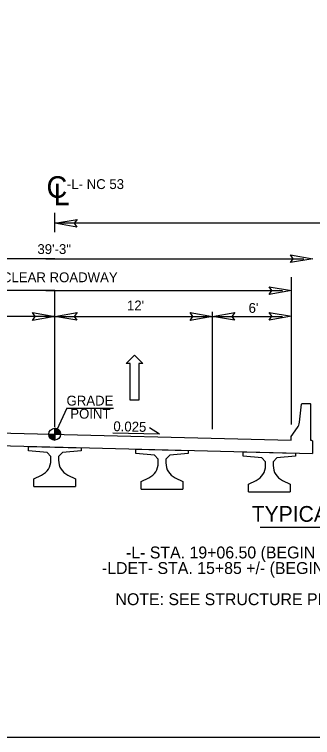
# Model space of a CAD drawing. Extents: x 1548135 to 1549339, y 868664 to 869085.
# Drawn here: x 1548186.8 to 1548209.5, y 868664.3 to 868719.3 of the extents above; entities that cross this region are included whole.
import ezdxf

# ---------------------------------------------------------------- set-up
doc = ezdxf.new("R2010")
doc.units = 0
for name, color, linetype in [('Default', 7, 'Continuous'), ('P_RDY_TC_Pvmt_Asphalt_Base_Course', 7, 'Continuous'), ('Sheet_Title_Block_Text', 7, 'Continuous'), ('Typical Bridge Rail CELL', 7, 'Continuous'), ('Typical Curb CELL', 7, 'Continuous'), ('Typical Grade Point Symbol CELL', 7, 'Continuous'), ('Typical Hinge Slope Arterial CELL', 7, 'Continuous'), ('Typical Hinge Slope Interstate CELL', 7, 'Continuous'), ('Typical Pavement Slope Information CELL', 7, 'Continuous'), ('Typical Shoulder Slope CELL', 7, 'Continuous'), ('Typical Shoulder Slope Information CELL', 7, 'Continuous'), ('Typical Terminator CELL', 7, 'Continuous'), ('Typical Text General CELL', 7, 'Continuous'), ('Typical Text ID Circle CELL', 7, 'Continuous')]:
    doc.layers.add(name, color=color, linetype=linetype)

msp = doc.modelspace()

# ---------------------------------------------------------------- linework, layer by layer
at = {"layer": 'Default'}
msp.add_lwpolyline([(1548135.05, 868774.324), (1548305.05, 868774.324), (1548305.05, 868664.324), (1548135.05, 868664.324)], close=True, dxfattribs=at)
at = {"layer": 'P_RDY_TC_Pvmt_Asphalt_Base_Course'}
for points in [[(1548191.54, 868703.148), (1548189.853, 868703.439), (1548191.55, 868703.739), (1548191.334, 868703.439)], [(1548207.801, 868701.037), (1548209.489, 868700.746), (1548207.792, 868700.446), (1548208.008, 868700.746)], [(1548206.176, 868698.613), (1548207.864, 868698.322), (1548206.167, 868698.022), (1548206.383, 868698.322)], [(1548188.165, 868696.642), (1548189.853, 868696.351), (1548188.156, 868696.051), (1548188.371, 868696.351)], [(1548191.54, 868696.061), (1548189.853, 868696.351), (1548191.55, 868696.651), (1548191.334, 868696.351)], [(1548200.165, 868696.642), (1548201.853, 868696.351), (1548200.156, 868696.051), (1548200.371, 868696.351)], [(1548203.54, 868696.061), (1548201.853, 868696.351), (1548203.55, 868696.651), (1548203.334, 868696.351)], [(1548206.176, 868696.66), (1548207.864, 868696.369), (1548206.167, 868696.069), (1548206.383, 868696.369)]]:
    msp.add_lwpolyline(points, close=True, dxfattribs=at)
at = {"layer": 'Typical Bridge Rail CELL'}
for p, q in [((1548187.853, 868686.13), (1548187.853, 868686.471)), ((1548187.853, 868686.471), (1548191.853, 868686.371)), ((1548189.269, 868686.005), (1548187.853, 868686.13)), ((1548189.561, 868685.713), (1548189.269, 868686.005)), ((1548190.436, 868686.005), (1548190.144, 868685.713)), ((1548191.853, 868686.13), (1548190.436, 868686.005)), ((1548191.853, 868686.371), (1548191.853, 868686.13)), ((1548196.019, 868685.926), (1548196.019, 868686.267)), ((1548196.019, 868686.267), (1548200.019, 868686.167)), ((1548200.019, 868686.167), (1548200.019, 868685.926)), ((1548204.186, 868685.721), (1548204.186, 868686.063)), ((1548204.186, 868686.063), (1548208.186, 868685.963)), ((1548208.186, 868685.963), (1548208.186, 868685.721)), ((1548189.561, 868685.413), (1548189.561, 868685.713)), ((1548190.144, 868685.713), (1548190.144, 868685.413)), ((1548197.436, 868685.801), (1548196.019, 868685.926)), ((1548197.728, 868685.509), (1548197.436, 868685.801)), ((1548197.728, 868685.209), (1548197.728, 868685.509)), ((1548198.603, 868685.801), (1548198.311, 868685.509)), ((1548198.311, 868685.509), (1548198.311, 868685.209)), ((1548200.019, 868685.926), (1548198.603, 868685.801)), ((1548205.603, 868685.596), (1548204.186, 868685.721)), ((1548205.894, 868685.305), (1548205.603, 868685.596)), ((1548206.769, 868685.596), (1548206.478, 868685.305)), ((1548208.186, 868685.721), (1548206.769, 868685.596)), ((1548205.894, 868685.005), (1548205.894, 868685.305)), ((1548206.478, 868685.305), (1548206.478, 868685.005)), ((1548188.269, 868684.005), (1548188.855, 868684.288)), ((1548188.269, 868683.421), (1548188.269, 868684.005)), ((1548190.85, 868684.288), (1548191.436, 868684.005)), ((1548191.436, 868684.005), (1548191.436, 868683.421)), ((1548196.436, 868683.801), (1548197.022, 868684.084)), ((1548196.436, 868683.217), (1548196.436, 868683.801)), ((1548199.017, 868684.084), (1548199.603, 868683.801)), ((1548199.603, 868683.801), (1548199.603, 868683.217)), ((1548204.603, 868683.596), (1548205.189, 868683.88)), ((1548207.183, 868683.88), (1548207.769, 868683.596)), ((1548188.269, 868683.421), (1548191.436, 868683.421)), ((1548196.436, 868683.217), (1548199.603, 868683.217)), ((1548204.603, 868683.013), (1548204.603, 868683.596)), ((1548207.769, 868683.596), (1548207.769, 868683.013)), ((1548204.603, 868683.013), (1548207.769, 868683.013))]:
    msp.add_line(p, q, dxfattribs=at)
for centre, start, end in [((1548188.311, 868685.413), 295.821, 0), ((1548191.394, 868685.413), 180, 244.179), ((1548196.478, 868685.209), 295.821, 0), ((1548199.561, 868685.209), 180, 244.179), ((1548204.644, 868685.005), 295.821, 0), ((1548207.728, 868685.005), 180, 244.179)]:
    msp.add_arc(centre, 1.25, start, end, dxfattribs=at)
at = {"layer": 'Typical Curb CELL'}
for p, q in [((1548189.853, 868687.399), (1548189.853, 868687.847)), ((1548189.405, 868687.399), (1548189.853, 868687.399)), ((1548189.852, 868686.952), (1548189.853, 868687.399)), ((1548189.853, 868687.399), (1548189.852, 868686.952)), ((1548190.3, 868687.399), (1548189.853, 868687.399))]:
    msp.add_line(p, q, dxfattribs=at)
for points in [[(1548189.857, 868687.847), (1548189.857, 868687.847), (1548189.857, 868687.399)], [(1548189.866, 868687.847), (1548189.866, 868687.399)], [(1548189.875, 868687.846), (1548189.875, 868687.399)], [(1548189.884, 868687.846), (1548189.884, 868687.399)], [(1548189.893, 868687.845), (1548189.893, 868687.399)], [(1548189.902, 868687.844), (1548189.902, 868687.399)], [(1548189.911, 868687.843), (1548189.911, 868687.399)], [(1548189.92, 868687.842), (1548189.92, 868687.399)], [(1548189.929, 868687.841), (1548189.929, 868687.399)], [(1548189.937, 868687.839), (1548189.937, 868687.399)], [(1548189.946, 868687.837), (1548189.946, 868687.399)], [(1548189.955, 868687.835), (1548189.955, 868687.399)], [(1548189.964, 868687.833), (1548189.964, 868687.399)], [(1548189.973, 868687.83), (1548189.973, 868687.399)], [(1548189.982, 868687.828), (1548189.982, 868687.399)], [(1548189.991, 868687.825), (1548189.991, 868687.399)], [(1548190, 868687.822), (1548190, 868687.399)], [(1548190.009, 868687.819), (1548190.009, 868687.399)], [(1548190.018, 868687.815), (1548190.018, 868687.399)], [(1548190.027, 868687.811), (1548190.027, 868687.399)], [(1548190.036, 868687.807), (1548190.036, 868687.399)], [(1548190.045, 868687.803), (1548190.045, 868687.399)], [(1548190.054, 868687.799), (1548190.054, 868687.399)], [(1548190.063, 868687.794), (1548190.063, 868687.399)], [(1548190.072, 868687.789), (1548190.072, 868687.399)], [(1548190.081, 868687.784), (1548190.081, 868687.399)], [(1548190.09, 868687.779), (1548190.09, 868687.399)], [(1548190.099, 868687.773), (1548190.099, 868687.399)], [(1548190.108, 868687.767), (1548190.108, 868687.399)], [(1548190.117, 868687.76), (1548190.117, 868687.399)], [(1548190.125, 868687.754), (1548190.125, 868687.399)], [(1548190.134, 868687.747), (1548190.134, 868687.399)], [(1548190.143, 868687.739), (1548190.143, 868687.399)], [(1548190.152, 868687.731), (1548190.152, 868687.399)], [(1548190.161, 868687.723), (1548190.161, 868687.399)], [(1548190.17, 868687.715), (1548190.17, 868687.399)], [(1548190.179, 868687.706), (1548190.179, 868687.399)], [(1548190.188, 868687.696), (1548190.188, 868687.399)], [(1548190.197, 868687.685), (1548190.197, 868687.399)], [(1548190.206, 868687.674), (1548190.206, 868687.399)], [(1548190.215, 868687.662), (1548190.215, 868687.399)], [(1548190.224, 868687.649), (1548190.224, 868687.399)], [(1548190.233, 868687.635), (1548190.233, 868687.399)], [(1548190.242, 868687.62), (1548190.242, 868687.399)], [(1548190.251, 868687.604), (1548190.251, 868687.399)], [(1548189.407, 868687.399), (1548189.407, 868687.35)], [(1548189.416, 868687.399), (1548189.416, 868687.298)], [(1548189.425, 868687.399), (1548189.425, 868687.266)], [(1548189.434, 868687.399), (1548189.434, 868687.239)], [(1548189.443, 868687.399), (1548189.443, 868687.218)], [(1548189.452, 868687.399), (1548189.452, 868687.199)], [(1548189.461, 868687.399), (1548189.461, 868687.182)], [(1548189.47, 868687.399), (1548189.47, 868687.166)], [(1548189.479, 868687.399), (1548189.479, 868687.153)], [(1548189.488, 868687.399), (1548189.488, 868687.14)], [(1548189.497, 868687.399), (1548189.497, 868687.128)], [(1548189.506, 868687.399), (1548189.506, 868687.117)], [(1548189.515, 868687.399), (1548189.515, 868687.106)], [(1548189.524, 868687.399), (1548189.524, 868687.096)], [(1548189.533, 868687.399), (1548189.533, 868687.086)], [(1548189.542, 868687.399), (1548189.542, 868687.077)], [(1548189.551, 868687.399), (1548189.551, 868687.069)], [(1548189.56, 868687.399), (1548189.56, 868687.061)], [(1548189.568, 868687.399), (1548189.568, 868687.053)], [(1548189.577, 868687.399), (1548189.577, 868687.046)], [(1548189.586, 868687.399), (1548189.586, 868687.039)], [(1548189.595, 868687.399), (1548189.595, 868687.033)], [(1548189.604, 868687.399), (1548189.604, 868687.027)], [(1548189.613, 868687.399), (1548189.613, 868687.021)], [(1548189.622, 868687.399), (1548189.622, 868687.015)], [(1548189.631, 868687.399), (1548189.631, 868687.01)], [(1548189.64, 868687.399), (1548189.64, 868687.005)], [(1548189.649, 868687.399), (1548189.649, 868687)], [(1548189.658, 868687.399), (1548189.658, 868686.996)], [(1548189.667, 868687.399), (1548189.667, 868686.992)], [(1548189.676, 868687.399), (1548189.676, 868686.988)], [(1548189.685, 868687.399), (1548189.685, 868686.984)], [(1548189.694, 868687.399), (1548189.694, 868686.98)], [(1548189.703, 868687.399), (1548189.703, 868686.977)], [(1548189.712, 868687.399), (1548189.712, 868686.975)], [(1548189.721, 868687.399), (1548189.721, 868686.971)], [(1548189.73, 868687.399), (1548189.73, 868686.97)], [(1548189.739, 868687.399), (1548189.739, 868686.967)], [(1548189.748, 868687.399), (1548189.748, 868686.965)], [(1548189.756, 868687.399), (1548189.756, 868686.963)], [(1548189.765, 868687.399), (1548189.765, 868686.961)], [(1548189.774, 868687.399), (1548189.774, 868686.959)], [(1548189.783, 868687.399), (1548189.783, 868686.958)], [(1548189.792, 868687.399), (1548189.792, 868686.956)], [(1548189.801, 868687.399), (1548189.801, 868686.955)], [(1548189.81, 868687.399), (1548189.81, 868686.954)], [(1548189.819, 868687.399), (1548189.819, 868686.953)], [(1548189.828, 868687.399), (1548189.828, 868686.953)], [(1548189.837, 868687.399), (1548189.837, 868686.952)], [(1548189.846, 868687.399), (1548189.846, 868686.952), (1548189.846, 868686.952)], [(1548190.26, 868687.585), (1548190.26, 868687.399)], [(1548190.269, 868687.564), (1548190.269, 868687.399)], [(1548190.278, 868687.539), (1548190.278, 868687.399)], [(1548190.287, 868687.509), (1548190.287, 868687.399)], [(1548190.296, 868687.463), (1548190.296, 868687.399)]]:
    msp.add_lwpolyline(points, dxfattribs=at)
msp.add_circle((1548189.852, 868687.399), 0.448, dxfattribs=at)
for start, end in [(359.9905, 89.9905), (179.9905, 269.9905)]:
    msp.add_arc((1548189.852, 868687.399), 0.448, start, end, dxfattribs=at)
at = {"layer": 'Typical Grade Point Symbol CELL'}
for p, q in [((1548189.853, 868702.765), (1548189.853, 868704.242)), ((1548236.801, 868703.439), (1548189.853, 868703.439)), ((1548189.853, 868700.746), (1548170.228, 868700.746)), ((1548189.165, 868700.746), (1548208.801, 868700.746)), ((1548207.864, 868688.145), (1548207.864, 868699.347)), ((1548189.853, 868698.322), (1548171.853, 868698.322)), ((1548189.165, 868698.322), (1548207.176, 868698.322)), ((1548189.853, 868687.949), (1548189.853, 868698.322)), ((1548201.853, 868687.768), (1548201.853, 868696.696)), ((1548189.853, 868696.351), (1548171.853, 868696.351)), ((1548189.165, 868696.351), (1548207.176, 868696.351)), ((1548202.853, 868696.351), (1548204.853, 868696.351))]:
    msp.add_line(p, q, dxfattribs=at)
at = {"layer": 'Typical Hinge Slope Arterial CELL'}
msp.add_line((1548190.777, 868689.386), (1548194.334, 868689.386), dxfattribs=at)
at = {"layer": 'Typical Pavement Slope Information CELL'}
for q in [(1548197.056, 868687.874), (1548194.269, 868687.486)]:
    msp.add_line((1548197.837, 868687.396), q, dxfattribs=at)
at = {"layer": 'Typical Shoulder Slope CELL'}
msp.add_line((1548190.777, 868689.386), (1548189.853, 868687.399), dxfattribs=at)
at = {"layer": 'Typical Shoulder Slope Information CELL'}
for p, q in [((1548195.294, 868692.787), (1548195.914, 868693.417)), ((1548195.914, 868693.417), (1548196.554, 868692.787)), ((1548195.594, 868692.787), (1548195.294, 868692.787)), ((1548195.594, 868689.987), (1548195.594, 868692.787)), ((1548196.554, 868692.787), (1548196.254, 868692.787)), ((1548196.254, 868692.787), (1548196.254, 868689.987)), ((1548196.254, 868689.987), (1548195.594, 868689.987))]:
    msp.add_line(p, q, dxfattribs=at)
at = {"layer": 'Typical Terminator CELL'}
msp.add_line((1548205.498, 868680.332), (1548227.219, 868680.332), dxfattribs=at)
at = {"layer": 'Typical Text ID Circle CELL'}
for p, q in [((1548208.484, 868688.302), (1548208.631, 868689.693)), ((1548208.631, 868689.693), (1548208.667, 868689.73)), ((1548208.667, 868689.73), (1548209.297, 868689.73)), ((1548209.297, 868689.73), (1548209.33, 868689.697)), ((1548209.33, 868689.697), (1548209.33, 868686.949)), ((1548171.853, 868687.849), (1548207.853, 868686.949)), ((1548207.853, 868687.21), (1548208.332, 868687.895)), ((1548207.853, 868686.949), (1548207.853, 868687.21)), ((1548170.245, 868686.912), (1548209.46, 868685.931)), ((1548209.33, 868686.949), (1548209.395, 868686.949)), ((1548209.395, 868686.949), (1548209.46, 868686.884)), ((1548209.46, 868686.884), (1548209.46, 868686.428)), ((1548209.46, 868686.428), (1548209.46, 868685.931))]:
    msp.add_line(p, q, dxfattribs=at)
msp.add_arc((1548207.62, 868688.393), 0.869, 325.0087, 353.9889, dxfattribs=at)

# ---------------------------------------------------------------- texts
at = {"layer": 'Sheet_Title_Block_Text'}
msp.add_text('C', height=1.64, dxfattribs=at).set_placement((1548189.226, 868705.378))
msp.add_text('L', height=1.641, rotation=359.9469, dxfattribs=at).set_placement((1548189.771, 868704.818))
at = {"layer": 'Typical Hinge Slope Arterial CELL'}
msp.add_text('  TYPICAL SECTION NO.  7', height=1.2, dxfattribs=at).set_placement((1548203.954, 868680.734))
at = {"layer": 'Typical Hinge Slope Interstate CELL'}
for s, p in [('-L- NC 53', (1548190.78, 868706.045)), ('39\'-3"', (1548188.535, 868701.102)), ("36' CLEAR ROADWAY", (1548184.251, 868698.957))]:
    msp.add_text(s, height=0.75, dxfattribs=at).set_placement(p)
at = {"layer": 'Typical Pavement Slope Information CELL'}
msp.add_text('0.025', height=0.75, rotation=358.568, dxfattribs=at).set_placement((1548194.307, 868687.634))
at = {"layer": 'Typical Shoulder Slope CELL'}
for s, p in [("12'", (1548195.352, 868696.812)), ("6' ", (1548204.607, 868696.626)), ('GRADE', (1548190.751, 868689.575)), ('POINT', (1548191.036, 868688.581))]:
    msp.add_text(s, height=0.75, dxfattribs=at).set_placement(p)
at = {"layer": 'Typical Text General CELL'}
for s, p in [('-L- STA. 19+06.50 (BEGIN BRIDGE) TO STA. 20+61.50 (END BRIDGE)', (1548195.275, 868677.949)), ('-LDET- STA. 15+85 +/- (BEGIN BRIDGE) TO STA. 18+85 +/- (END BRIDGE)', (1548193.444, 868676.764)), ('NOTE: SEE STRUCTURE PLANS FOR STRUCTURE CONSTRUCTION DETAILS', (1548194.479, 868674.394))]:
    msp.add_text(s, height=0.90387, dxfattribs=at).set_placement(p)

doc.saveas('drawing.dxf')
